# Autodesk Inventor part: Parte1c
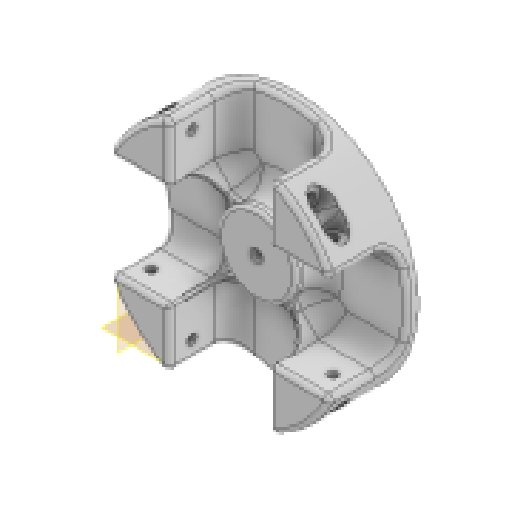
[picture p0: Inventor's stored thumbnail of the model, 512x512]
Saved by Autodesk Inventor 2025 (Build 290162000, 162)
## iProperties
Created: 2025-05
Part Number: Parte1c
Material: Generico
Document SubType Name: Modeling
Designer: R5800u
Density: 1 g/cm^3
Appearance: Default
Author: R5800u
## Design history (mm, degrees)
sketch "Schizzo1" dims "d0" = 100
  geometry: L1 (0, 0)-(35.355, 35.355); L2 (0, 0)-(50, 0); L3 (20.572, 20.572)-(20.572, 45.572); L4 (20.572, 20.572)-(45.572, 20.572); L5 (0, 0)-(0, 44.829) reference; L6 (-20.572, 20.572)-(-20.572, 45.572); L7 (0, 0)-(-35.355, 35.355); L8 (-20.572, 20.572)-(-45.572, 20.572); L9 (0, 0)-(56.569, 0); L10 (26.572, 42.355)-(26.572, 26.572); L11 (26.572, 26.572)-(42.355, 26.572); L12 (-26.572, 42.355)-(-26.572, 26.572); L13 (-26.572, 26.572)-(-42.355, 26.572); L14 (-20.572, 24.815)-(0, 4.243); L15 (0, 4.243)-(20.572, 24.815); L16 (24.815, 20.572)-(0, -4.243); L17 (0, -4.243)-(-24.815, 20.572); L18 (20.572, -20.572)-(20.572, -45.572); L19 (0, -4.243)-(20.572, -24.815); L20 (26.572, -42.355)-(26.572, -26.572); L21 (24.815, -20.572)-(0, 4.243); L22 (0, 0)-(35.355, -35.355); L23 (26.572, -26.572)-(42.355, -26.572); L24 (20.572, -20.572)-(45.572, -20.572); L25 (0, 0)-(0, -44.829); L26 (-20.572, -24.815)-(0, -4.243); L27 (0, 4.243)-(-24.815, -20.572); L28 (0, 0)-(-35.355, -35.355); L29 (-20.572, -20.572)-(-20.572, -45.572); L30 (-26.572, -42.355)-(-26.572, -26.572); L31 (-26.572, -26.572)-(-42.355, -26.572); L32 (-20.572, -20.572)-(-45.572, -20.572); 3 further points
  constraints: 64 end point, 25 symmetric about line, 13 point on line, 3 vertical, 2 coincident, 2 horizontal, 1 equal length, 9 other
  dimensions: "d1" = 45 deg angle of L2 L1; "d3" = 25 distance of L3.start L4.end; "d8" = 6 distance between parallel lines of L3 L10; "d9" = 6 distance between parallel lines of L6 L12; "d10" = 3 distance between parallel lines of L7 L14; "d11" = 3 distance between parallel lines of L1 L16; "d22" = 6 distance between parallel lines of L4 L11; "d23" = 6 distance between parallel lines of L8 L13
extrude "Estrusione1" new body sketch "Schizzo1" stored distance "d4" = 75; taper "d5" = 0 deg
node "Piano di lavoro1"
sketch "Schizzo3" dims "d24" = 100
  geometry: L1 (0, 0)-(35.355, 35.355); L2 (0, 0)-(50, 0); L3 (20.572, 20.572)-(20.572, 45.572); L4 (20.572, 20.572)-(45.572, 20.572); L5 (0, 0)-(0, 44.829); L6 (-20.572, 20.572)-(-20.572, 45.572); L7 (0, 0)-(-35.355, 35.355); L8 (-20.572, 20.572)-(-45.572, 20.572); L9 (0, 0)-(56.569, 0); L10 (26.572, 42.355)-(26.572, 26.572); L11 (26.572, 26.572)-(42.355, 26.572); L12 (-26.572, 42.355)-(-26.572, 26.572); L13 (-26.572, 26.572)-(-42.355, 26.572); L14 (-20.572, 24.815)-(0, 4.243); L15 (0, 4.243)-(20.572, 24.815); L16 (24.815, 20.572)-(0, -4.243); L17 (0, -4.243)-(-24.815, 20.572); L18 (20.572, -20.572)-(20.572, -45.572); L19 (0, -4.243)-(20.572, -24.815); L20 (26.572, -42.355)-(26.572, -26.572); L21 (24.815, -20.572)-(0, 4.243); L22 (0, 0)-(35.355, -35.355); L23 (26.572, -26.572)-(42.355, -26.572); L24 (20.572, -20.572)-(45.572, -20.572); L25 (0, 0)-(0, -44.829); L26 (-20.572, -24.815)-(0, -4.243); L27 (0, 4.243)-(-24.815, -20.572); L28 (0, 0)-(-35.355, -35.355); L29 (-20.572, -20.572)-(-20.572, -45.572); L30 (-26.572, -42.355)-(-26.572, -26.572); L31 (-26.572, -26.572)-(-42.355, -26.572); L32 (-20.572, -20.572)-(-45.572, -20.572); 16 further points
  constraints: 64 end point, 25 symmetric about line, 13 point on line, 2 coincident, 2 horizontal, 2 parallel, 2 vertical, 1 equal length, 9 other
  dimensions: "d25" = 45 deg angle of L2 L1; "d26" = 25 distance of L3.start L4.end; "d27" = 6 distance between parallel lines of L3 L10; "d28" = 6 distance between parallel lines of L6 L12; "d29" = 3 distance between parallel lines of L7 L14; "d30" = 3 distance between parallel lines of L1 L16; "d31" = 6 distance between parallel lines of L4 L11; "d32" = 6 distance between parallel lines of L8 L13; "d41" = 3 distance between parallel lines of L1 L15; "d42" = 3 distance between parallel lines of L7 L17; "d63" = 25 distance of L18.start L24.end (derived); "d64" = 25 distance of L18.start L18.end (derived); "d65" = 41.14378 distance between parallel lines of L32 L8 (derived); "d66" = 41.14378 distance between parallel lines of L24 L4 (derived); "d67" = 41.14378 distance between parallel lines of L3 L6 (derived); "d68" = 41.14378 distance between parallel lines of L18 L29 (derived)
extrude "Estrusione4" cut sketch "Schizzo3" extent not by distance; stored distance "d33" = 30; taper "d34" = 0 deg
sketch "Schizzo4"
  geometry: L1 (45.572, 37.5)-(45.572, 3) reference; L2 (45.572, 20.25)-(0, 20.25); L3 (0, 3)-(0, 37.5) reference; C1 r 2 at (37, 20.25); 2 further points
  constraints: 2 end point, 2 midpoint, 1 centre point, 1 coincident, 1 point on line
  dimensions: "d36" = 37 horizontal distance of point (0, 0) point (37, 20.25); "d37" = 4 diameter of C1
extrude "Estrusione5" cut sketch "Schizzo4" extent not by distance; stored distance "d38" = 0; taper "d39" = 0 deg
pattern_circular "Serie circolare1" dims angle "d47" = 360 deg
sketch "Schizzo5"
  geometry: C1 r 50 at (0, 0) reference; 1 further point
extrude "Estrusione6" cut sketch "Schizzo5" distance "d53" = 36; taper "d54" = 0 deg
sketch "Schizzo6"
  geometry: L1 (45.572, -20.572)-(20.572, -20.572) reference; L2 (20.572, 20.572)-(45.572, 20.572) reference; L3 (20.572, 45.572)-(20.572, 20.572) reference; L4 (-20.572, 20.572)-(-20.572, 45.572) reference; L5 (-45.572, 20.572)-(-20.572, 20.572) reference; L6 (-20.572, -20.572)-(-45.572, -20.572) reference; L7 (-20.572, -45.572)-(-20.572, -20.572) reference; L8 (20.572, -20.572)-(20.572, -45.572) reference; L9 (-20.572, 24.815)-(-24.815, 20.572); L10 (-24.815, 20.572)-(-20.572, 24.815); L11 (-24.815, -20.572)-(-20.572, -24.815); L12 (20.572, 24.815)-(24.815, 20.572); L13 (24.815, -20.572)-(20.572, -24.815); C1 r 16 at (0, 0); A1 r 50 centre (0, 0) between (45.572, 20.572) and (20.572, 45.572) reference; A2 r 50 centre (0, 0) between (-20.572, 45.572) and (-45.572, 20.572) reference; A3 r 50 centre (0, 0) between (-45.572, -20.572) and (-20.572, -45.572) reference; A4 r 50 centre (0, 0) between (20.572, -45.572) and (45.572, -20.572) reference; A5 r 35 centre (0, 53.131) between (-20.572, 24.815) and (20.572, 24.815); A6 r 35 centre (-53.131, 0) between (-24.815, -20.572) and (-24.815, 20.572); A7 r 35 centre (0, -53.131) between (20.572, -24.815) and (-20.572, -24.815); A8 r 35 centre (53.131, 0) between (24.815, 20.572) and (24.815, -20.572); 1 further point
  constraints: 10 end point, 8 point on circle, 5 centre point, 1 coincident, 1 parallel, 1 perpendicular, 17 other
  dimensions: "d55" = 32 diameter of C1; "d109" = 35 radius of A5; "d112" = 360 deg dimension on point (0, 0) A5.centre (derived)
extrude "Estrusione7" join sketch "Schizzo6" stored distance "d56" = 36; taper "d57" = 0 deg
sketch "Schizzo7"
  geometry: C1 r 2.5 at (0, 0); 1 further point
  constraints: 1 centre point, 1 coincident
  dimensions: "d69" = 5 diameter of C1
extrude "Estrusione8" cut sketch "Schizzo7" extent not by distance; stored distance "d70" = 10; taper "d71" = 0 deg
sketch "Schizzo8"
  geometry: L1 (20.572, 20.572)-(45.572, 20.572) reference; L2 (20.572, 45.572)-(20.572, 20.572) reference; L3 (-20.572, 20.572)-(-20.572, 45.572) reference; L4 (-45.572, 20.572)-(-20.572, 20.572) reference; L5 (-20.572, -20.572)-(-45.572, -20.572) reference; L6 (-20.572, -45.572)-(-20.572, -20.572) reference; L7 (20.572, -20.572)-(20.572, -45.572) reference; L8 (45.572, -20.572)-(20.572, -20.572) reference; A1 r 50 centre (0, 0) between (45.572, 20.572) and (20.572, 45.572) reference; A2 r 50 centre (0, 0) between (20.572, -45.572) and (45.572, -20.572) reference; A3 r 50 centre (0, 0) between (-45.572, -20.572) and (-20.572, -45.572) reference; A4 r 50 centre (0, 0) between (-20.572, 45.572) and (-45.572, 20.572) reference; A5 r 35 centre (0, 53.131) between (-20.572, 24.815) and (20.572, 24.815); A6 r 35 centre (-53.131, 0) between (-24.815, -20.572) and (-24.815, 20.572); A7 r 35 centre (0, -53.131) between (20.572, -24.815) and (-20.572, -24.815); A8 r 35 centre (53.131, 0) between (24.815, 20.572) and (24.815, -20.572); 9 further points
  constraints: 8 point on circle, 4 centre point, 17 other
  dimensions: "d104" = 35 radius of A5; "d107" = 360 deg dimension on point (0, 0) A5.centre (derived)
extrude "Estrusione9" cut sketch "Schizzo8" distance "d72" = 8; taper "d73" = 0 deg
node "Piano di lavoro3"
sketch "Schizzo10"
  geometry: C1 r 2 at (-17.25, 8.572) reference; C2 r 4.25 at (-17.25, 8.572); 1 further point
  constraints: 1 centre point, 1 coincident
  dimensions: "d86" = 8.5 diameter of C2
extrude "Estrusione11" cut sketch "Schizzo10" distance "d87" = 13; taper "d88" = 0 deg
node "Piano di lavoro4"
sketch "Schizzo11"
  geometry: C1 r 2 at (8.572, -17.25) reference; C2 r 4.25 at (8.572, -17.25); 1 further point
  constraints: 1 centre point, 1 coincident
  dimensions: "d90" = 8.5 diameter of C2
extrude "Estrusione12" cut sketch "Schizzo11" distance "d91" = 13; taper "d92" = 0 deg
pattern_circular "Serie circolare4" dims "d94" = 360 deg
sketch "Schizzo12"
  geometry: C1 r 2.5 at (0, 0) reference; C2 r 6 at (0, 0); 1 further point
  constraints: 1 centre point, 1 coincident
  dimensions: "d128" = 12 diameter of C2
extrude "Estrusione13" cut sketch "Schizzo12" distance "d129" = 13; taper "d130" = 0 deg
sketch "Schizzo14"
  geometry: C1 r 6 at (0, 0) reference; C2 r 16 at (0, 0) reference; C3 r 2.5 at (0, 0) reference; C4 r 20 at (0, 0); 1 further point
  constraints: 1 centre point, 1 coincident
  dimensions: "d133" = 40 diameter of C4
extrude "Estrusione14" cut sketch "Schizzo14" distance "d131" = 15; taper "d132" = 0 deg
sketch "Schizzo17"
  geometry: L1 (-45.572, -20.572)-(-20.572, -20.572) reference; L2 (-20.572, -20.572)-(-20.572, -45.572) reference; L3 (20.572, -45.572)-(20.572, -20.572) reference; L4 (20.572, -20.572)-(45.572, -20.572) reference; L5 (45.572, 20.572)-(20.572, 20.572) reference; L6 (20.572, 20.572)-(20.572, 45.572) reference; L7 (-20.572, 45.572)-(-20.572, 20.572) reference; L8 (-20.572, 20.572)-(-45.572, 20.572) reference; L9 (20.572, 20.572)-(0, 0); L10 (21.986, 20.572)-(0.707, -0.707); L11 (20.572, 21.986)-(-0.707, 0.707); C1 r 16 at (0, 0) reference; C2 r 2.5 at (0, 0) reference; A1 r 50 centre (0, 0) between (-20.572, -45.572) and (20.572, -45.572) reference; A2 r 50 centre (0, 0) between (45.572, -20.572) and (45.572, 20.572) reference; A3 r 50 centre (0, 0) between (20.572, 45.572) and (-20.572, 45.572) reference; A4 r 50 centre (0, 0) between (-45.572, 20.572) and (-45.572, -20.572) reference; 3 further points
  constraints: 6 end point, 2 parallel, 2 point on line
  dimensions: "d149" = 1 distance between parallel lines of L9 L10; "d150" = 1 distance between parallel lines of L9 L11
extrude "Estrusione16" join sketch "Schizzo17" distance "d151" = 10; taper "d152" = 0 deg
pattern_circular "Serie circolare9" dims angle "d154" = 360 deg
fillet "Raccordo32" dims "d164" = 8
fillet "Raccordo33" dims "d165" = 9.9
fillet "Raccordo34" dims "d166" = 2
fillet "Raccordo35" dims "d167" = 2
fillet "Raccordo36" dims "d168" = 1
fillet "Raccordo37" dims "d169" = 1.5
fillet "Raccordo38" dims "d170" = 3
fillet "Raccordo39" dims "d171" = 5
fillet "Raccordo40" dims "d172" = 0.2
feature "ھ耀ۀ耀ۂ耀ۄ耀ۆ耀ۈ耀ۊ耀ی耀" dims "d0" = 100, "d1" = 45 deg, "d3" = 25, "d4" = 75, "d5" = 0, "d8" = 6, "d9" = 6, "d10" = 3, "d11" = 3, "d12" = 3, "d18" = 2, "d19" = 2, "d22" = 6, "d23" = 6, "d24" = 100, "d25" = 45 deg, "d26" = 25, "d27" = 6, "d28" = 6, "d29" = 3, "d30" = 3, "d31" = 6, "d32" = 6, "d33" = 30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
node "Solido1"
node "Linea chiusa proiettata1"
node "Schizzo - Serie circolare1" dims "d107" = 360 deg (derived)
node "Linea chiusa proiettata2"
node "Schizzo - Serie circolare2" dims "d112" = 360 deg (derived)
node "Linea chiusa proiettata3"
node "Linea chiusa proiettata4"
